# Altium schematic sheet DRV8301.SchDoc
size 558 x 431 mm; Engineer: Nicholas Oborny; Revision: A.1; Name: Nicholas Oborny; Start Date: 7/23/2012
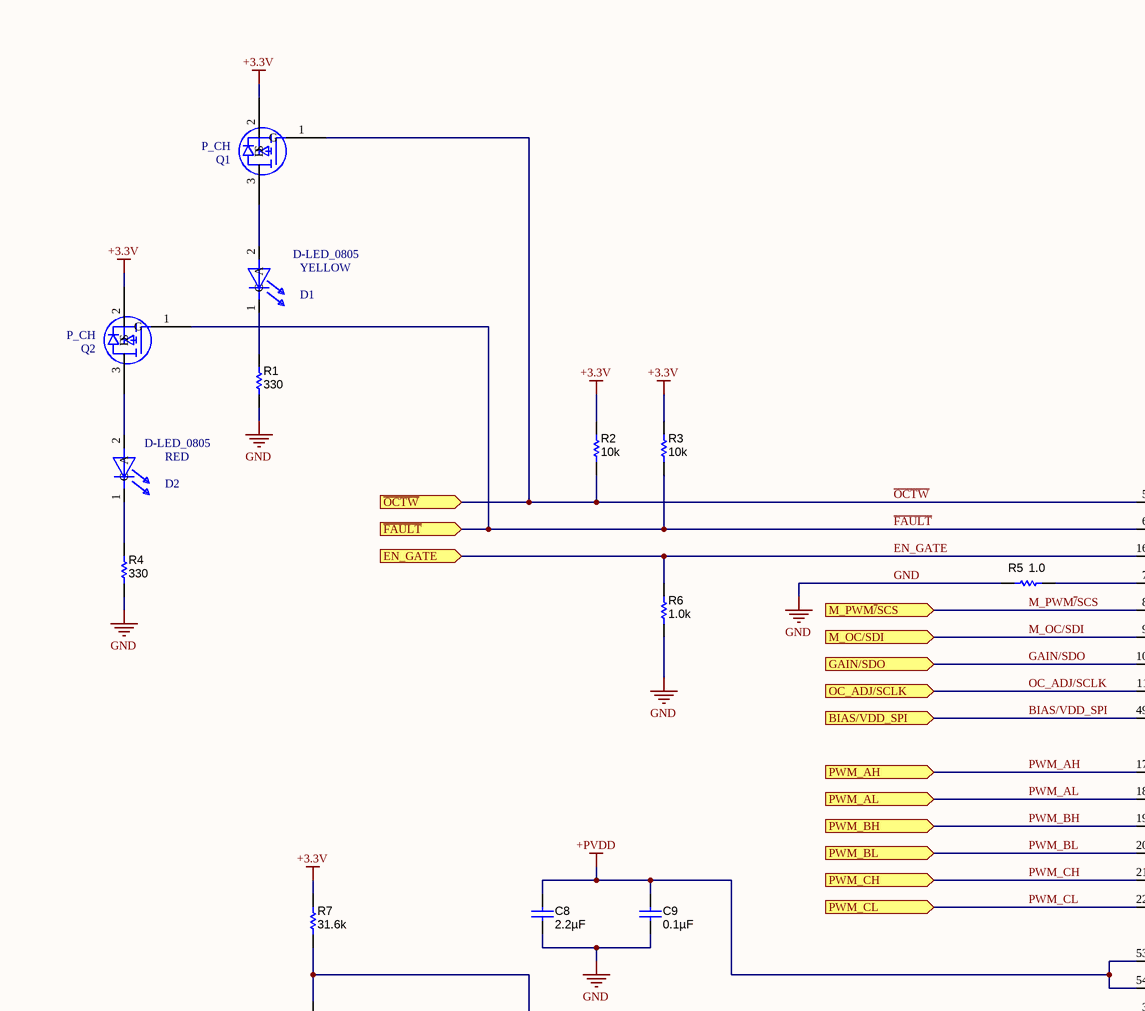
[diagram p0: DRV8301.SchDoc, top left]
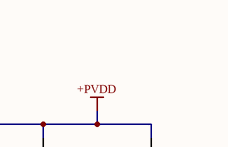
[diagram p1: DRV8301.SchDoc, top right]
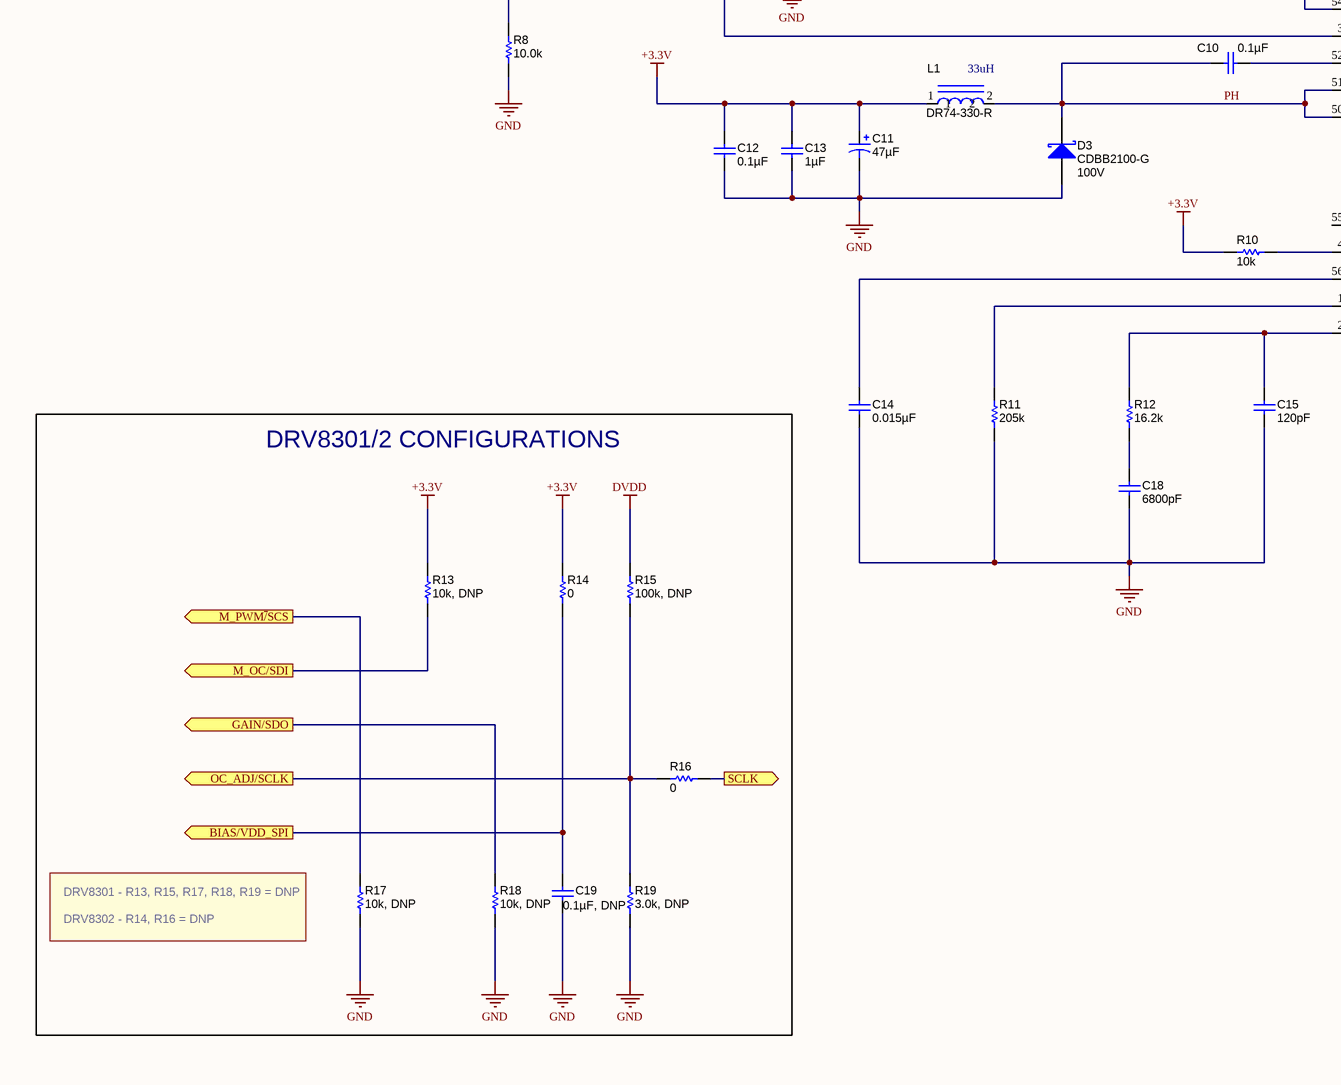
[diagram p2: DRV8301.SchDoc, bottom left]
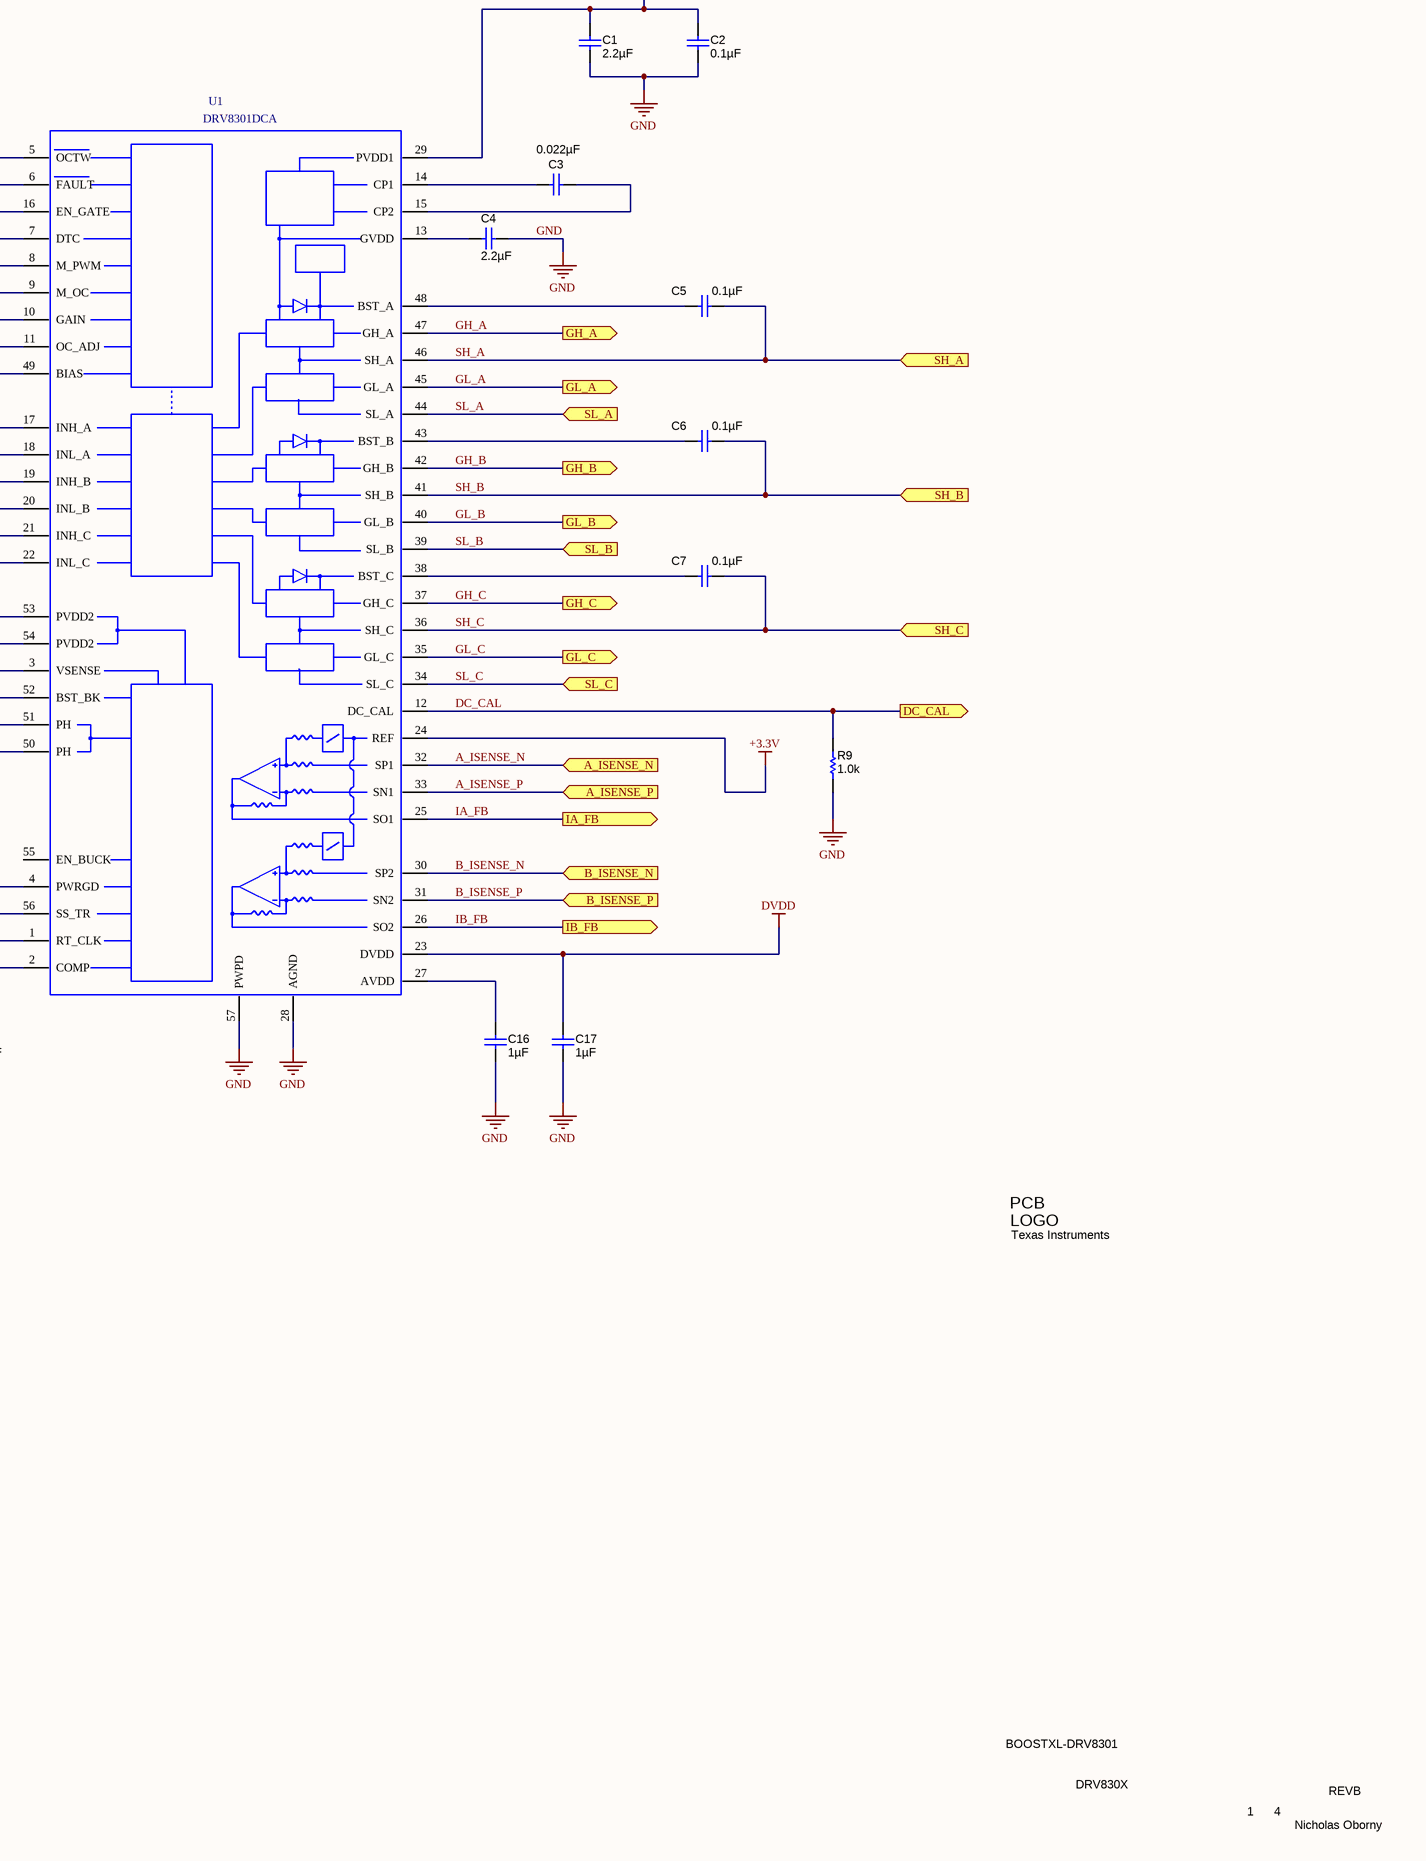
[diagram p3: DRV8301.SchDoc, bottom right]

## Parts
C1  ValueDisplayed: 2.2µF  [1210L]  (hidden comment: GRM32ER72A225KA35L)
C2  ValueDisplayed: 0.1µF  [0603L]  (hidden comment: GRM188R72A104KA35D)
C3  ValueDisplayed: 0.022µF  [0603L]  (hidden comment: C1608X7R1H223K)
C4  ValueDisplayed: 2.2µF  [0805L]  (hidden comment: GRM219R61E225KA12D)
C5  ValueDisplayed: 0.1µF  [0603L]  (hidden comment: C1608X7R1H104K)
C6  ValueDisplayed: 0.1µF  [0603L]  (hidden comment: C1608X7R1H104K)
C7  ValueDisplayed: 0.1µF  [0603L]  (hidden comment: C1608X7R1H104K)
C8  ValueDisplayed: 2.2µF  [1210L]  (hidden comment: GRM32ER72A225KA35L)
C9  ValueDisplayed: 0.1µF  [0603L]  (hidden comment: GRM188R72A104KA35D)
C10  ValueDisplayed: 0.1µF  [0603L]  (hidden comment: C1608X7R1H104K)
C11  ValueDisplayed: 47µF  [SM_RADIAL_D]  (hidden comment: EEE-FK1E470P)
C12  ValueDisplayed: 0.1µF  [0603L]  (hidden comment: C1608X7R1E104K)
C13  ValueDisplayed: 1µF  [0603L]  (hidden comment: C1608X5R1E105K080AC)
C14  ValueDisplayed: 0.015µF  [0603L]  (hidden comment: GRM188R71H153KA01D)
C15  ValueDisplayed: 120pF  [0603L]  (hidden comment: GRM1885C1H121JA01D)
C16  ValueDisplayed: 1µF  [0603L]  (hidden comment: GRM188R61E105KA12D)
C17  ValueDisplayed: 1µF  [0603L]  (hidden comment: GRM188R61E105KA12D)
C18  ValueDisplayed: 6800pF  [0603L]  (hidden comment: GRM188R71H682KA01D)
C19  ValueDisplayed: 0.1µF, DNP  [0603L]  (hidden comment: C1608X7R1E104K)
D1  D-LED_0805  value YELLOW  [LED_0805]
D2  D-LED_0805  value RED  [LED_0805]
D3  CDBB2100-G  value 100V  [SMB]
L1  DR74-330-R  value 33uH  [IND_DR74]
Logo1  Texas Instruments  [TI_Symbol_Overlay_Small]  (no BOM)
Q1  value P_CH  [SOT-23]  (hidden comment: TR_PFET_SOT23)
Q2  value P_CH  [SOT-23]  (hidden comment: TR_PFET_SOT23)
R1  value 330  [0603L]  (hidden comment: CRCW0603330RJNEA)
R2  value 10k  [0603L]  (hidden comment: CRCW060310K0JNEA)
R3  value 10k  [0603L]  (hidden comment: CRCW060310K0JNEA)
R4  value 330  [0603L]  (hidden comment: CRCW0603330RJNEA)
R5  value 1.0  [0603L]  (hidden comment: CRCW06031R00JNEA)
R6  value 1.0k  [0603L]  (hidden comment: CRCW06031K00JNEA)
R7  value 31.6k  [0603L]  (hidden comment: CRCW060331K6FKEA)
R8  value 10.0k  [0603L]  (hidden comment: RG1608P-103-B-T5)
R9  value 1.0k  [0603L]  (hidden comment: CRCW06031K00JNEA)
R10  value 10k  [0603L]  (hidden comment: CRCW060310K0JNEA)
R11  value 205k  [0603L]  (hidden comment: CRCW0603205KFKEA)
R12  value 16.2k  [0603L]  (hidden comment: CRCW060316K2FKEA)
R13  value 10k, DNP  [0603L]  (hidden comment: CRCW060310K0JNEA)
R14  value 0  [0603L]  (hidden comment: CRCW06030000Z0EA)
R15  value 100k, DNP  [0603L]  (hidden comment: CRCW0603100KJNEA)
R16  value 0  [0603L]  (hidden comment: CRCW06030000Z0EA)
R17  value 10k, DNP  [0603L]  (hidden comment: CRCW060310K0JNEA)
R18  value 10k, DNP  [0603L]  (hidden comment: CRCW060310K0JNEA)
R19  value 3.0k, DNP  [0603L]  (hidden comment: CRCW06033K00JNEA)
U1  DRV8301DCA  [DCA_56P]

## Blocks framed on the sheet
DRV8301/2 CONFIGURATIONS: C19 R13-R19

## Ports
A_ISENSE_N, A_ISENSE_P, B_ISENSE_N, B_ISENSE_P, BIAS/VDD_SPI, DC_CAL, EN_GATE, GAIN/SDO, GH_A, GH_B, GH_C, GL_A, GL_B, GL_C, IA_FB, IB_FB, M_OC/SDI, M_PWM~{/}SCS, OC_ADJ/SCLK, PWM_AH, PWM_AL, PWM_BH, PWM_BL, PWM_CH, PWM_CL, SCLK, SH_A, SH_B, SH_C, SL_A, SL_B, SL_C, ~{FAULT}, ~{OCTW}

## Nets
+3.3V: C11.1(+) C12.1 C13.1 L1.1 Q1.2(S) Q2.2(S) R2.2 R3.2 R7.2 R10.2 R13.2 R14.2 U1.24(REF)
+PVDD: C1.1 C2.1 C8.1 C9.1 U1.29(PVDD1) U1.53(PVDD2) U1.54(PVDD2)
DVDD: C17.1 R15.1 U1.23(DVDD)
GND: C1.2 C2.2 C4.2 C8.2 C9.2 C11.2(-) C12.2 C13.2 C14.2 C15.2 C16.2 C17.2 C18.2 C19.2 D3.2(A) R1.1 R4.1 R5.1 R6.1 R8.1 R9.1 R11.1 R17.1 R18.1 R19.1 U1.28(AGND) U1.57(PWPD)
~{FAULT}: Q2.1(G) R3.1 U1.6(FAULT) ; port ~{FAULT}
~{OCTW}: Q1.1(G) R2.1 U1.5(OCTW) ; port ~{OCTW}
A_ISENSE_N: U1.32(SP1) ; port A_ISENSE_N
A_ISENSE_P: U1.33(SN1) ; port A_ISENSE_P
B_ISENSE_N: U1.30(SP2) ; port B_ISENSE_N
B_ISENSE_P: U1.31(SN2) ; port B_ISENSE_P
BIAS/VDD_SPI: C19.1 R14.1 U1.49(BIAS) ; port BIAS/VDD_SPI
DC_CAL: R9.2 U1.12(DC_CAL) ; port DC_CAL
EN_GATE: R6.2 U1.16(EN_GATE) ; port EN_GATE
GAIN/SDO: R18.2 U1.10(GAIN) ; port GAIN/SDO
GH_A: U1.47(GH_A) ; port GH_A
GH_B: U1.42(GH_B) ; port GH_B
GH_C: U1.37(GH_C) ; port GH_C
GL_A: U1.45(GL_A) ; port GL_A
GL_B: U1.40(GL_B) ; port GL_B
GL_C: U1.35(GL_C) ; port GL_C
IA_FB: U1.25(SO1) ; port IA_FB
IB_FB: U1.26(SO2) ; port IB_FB
M_OC/SDI: R13.1 U1.9(M_OC) ; port M_OC/SDI
M_PWM~{/}SCS: R17.2 U1.8(M_PWM) ; port M_PWM~{/}SCS
OC_ADJ/SCLK: R15.2 R16.2 R19.2 U1.11(OC_ADJ) ; port OC_ADJ/SCLK
PH: C10.1 D3.1(K) L1.2 U1.50(PH) U1.51(PH)
PWM_AH: U1.17(INH_A) ; port PWM_AH
PWM_AL: U1.18(INL_A) ; port PWM_AL
PWM_BH: U1.19(INH_B) ; port PWM_BH
PWM_BL: U1.20(INL_B) ; port PWM_BL
PWM_CH: U1.21(INH_C) ; port PWM_CH
PWM_CL: U1.22(INL_C) ; port PWM_CL
SCLK: R16.1 ; port SCLK
SH_A: C5.2 U1.46(SH_A) ; port SH_A
SH_B: C6.2 U1.41(SH_B) ; port SH_B
SH_C: C7.2 U1.36(SH_C) ; port SH_C
SL_A: U1.44(SL_A) ; port SL_A
SL_B: U1.39(SL_B) ; port SL_B
SL_C: U1.34(SL_C) ; port SL_C
NetC3_1: C3.1 U1.14(CP1)
NetC3_2: C3.2 U1.15(CP2)
NetC4_1: C4.1 U1.13(GVDD)
NetC5_1: C5.1 U1.48(BST_A)
NetC6_1: C6.1 U1.43(BST_B)
NetC7_1: C7.1 U1.38(BST_C)
NetC10_2: C10.2 U1.52(BST_BK)
NetC14_1: C14.1 U1.56(SS_TR)
NetC15_1: C15.1 R12.2 U1.2(COMP)
NetC16_1: C16.1 U1.27(AVDD)
NetC18_1: C18.1 R12.1
NetD1_1: D1.1(C) R1.2
NetD1_2: D1.2(A) Q1.3(D)
NetD2_1: D2.1(C) R4.2
NetD2_2: D2.2(A) Q2.3(D)
NetR5_2: R5.2 U1.7(DTC)
NetR7_1: R7.1 R8.2 U1.3(VSENSE)
NetR10_1: R10.1 U1.4(PWRGD)
NetR11_2: R11.2 U1.1(RT_CLK)

Not connected (* = marked no-connect by the designer): U1 55(EN_BUCK)

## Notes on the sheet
- DRV8301 - R13, R15, R17, R18, R19 = DNP
- DRV8302 - R14, R16 = DNP
- BOOSTXL-DRV8301
- DRV830X
- 1
- 4
- REVB
- Nicholas Oborny

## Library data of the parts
C1 C8 = GRM32ER72A225KA35L: CAP, CERM, 2.2uF, 100V, +/-10%, X7R, 1210; Manufacturer: MuRata; Polarized: N; CompType: Capacitor; U/M: EA; Cap_F: 0.0000022; Tolerance_%: 10; ESR_Ohm: 0.007; Value1: 0.007 ohm; VDC_V: 100; IRMS_A: 4.4; TaMin_C: -55; TaMax_C: 125; Cap_Case: 1210
C2 C9 = GRM188R72A104KA35D: CAP, CERM, 0.1uF, 100V, +/-10%, X7R, 0603; Manufacturer: MuRata; Polarized: N; CompType: Capacitor; U/M: EA; Cap_F: 0.0000001; Tolerance_%: 10; Value1: Unknown; VDC_V: 100; TaMin_C: -55; TaMax_C: 125; Cap_Case: 0603
C3 = C1608X7R1H223K: CAP, CERM, 0.022uF, 50V, +/-10%, X7R, 0603; Manufacturer: TDK; Polarized: N; CompType: Capacitor; U/M: EA; Cap_F: 0.000000022; Tolerance_%: 10; ESR_Ohm: 0.0383; Value1: 0.0383 ohm; VDC_V: 50; TaMin_C: -55; TaMax_C: 125; Cap_Case: 0603
C4 = GRM219R61E225KA12D: CAP, CERM, 2.2uF, 25V, +/-10%, X5R, 0805; Manufacturer: MuRata; Polarized: N; CompType: Capacitor; U/M: EA; Cap_F: 0.0000022; Tolerance_%: 10; ESR_Ohm: 0.006; Value1: 0.006 ohm; VDC_V: 25; TaMin_C: -55; TaMax_C: 85; Cap_Case: 0805
C5-C7 C10 = C1608X7R1H104K: CAP, CERM, 0.1uF, 50V, +/-10%, X7R, 0603; Manufacturer: TDK; Polarized: N; CompType: Capacitor; U/M: EA; Cap_F: 0.0000001; Tolerance_%: 10; ESR_Ohm: 0.017; Value1: 0.017 ohm; VDC_V: 50; TaMin_C: -55; TaMax_C: 125; Cap_Case: 0603
C11 = EEE-FK1E470P: CAP, AL, 47uF, 25V, +/-20%, 0.36 ohm, SMD; Manufacturer: Panasonic; Polarized: Y; CompType: Capacitor; U/M: EA; Cap_F: 0.000047; Tolerance_%: 20; VDC_V: 25; ESR_Ohm: 0.36; IRMS_A: 0.24; TaMin_C: -55; TaMax_C: 105; Cap_Case: D
C12 C19 = C1608X7R1E104K: CAP, CERM, 0.1uF, 25V, +/-10%, X7R, 0603; Manufacturer: TDK; Polarized: N; CompType: Capacitor; U/M: EA; Cap_F: 0.0000001; Tolerance_%: 10; ESR_Ohm: 0.017; Value1: 0.017 ohm; VDC_V: 25; TaMin_C: -55; TaMax_C: 125; Cap_Case: 0603
C13 = C1608X5R1E105K080AC: CAP, CERM, 1uF, 25V, +/-10%, X5R, 0603; Manufacturer: TDK; Polarized: N; CompType: Capacitor; U/M: EA; Cap_F: 0.000001; Tolerance_%: 10; Value1: Unknown; VDC_V: 25; TaMin_C: -55; TaMax_C: 85; Cap_Case: 0603
C14 = GRM188R71H153KA01D: CAP, CERM, 0.015uF, 50V, +/-10%, X7R, 0603; Manufacturer: MuRata; Polarized: N; CompType: Capacitor; U/M: EA; Cap_F: 0.000000015; Tolerance_%: 10; Value1: Unknown; VDC_V: 50; TaMin_C: -55; TaMax_C: 125; Cap_Case: 0603
C15 = GRM1885C1H121JA01D: CAP, CERM, 120pF, 50V, +/-5%, C0G/NP0, 0603; Manufacturer: MuRata; Polarized: N; CompType: Capacitor; U/M: EA; Cap_F: 0.00000000012; Tolerance_%: 5; Value1: Unknown; VDC_V: 50; TaMin_C: -55; TaMax_C: 125; Cap_Case: 0603
C16 C17 = GRM188R61E105KA12D: CAP, CERM, 1uF, 25V, +/-10%, X5R, 0603; Manufacturer: MuRata; Polarized: N; CompType: Capacitor; U/M: EA; Cap_F: 0.000001; Tolerance_%: 10; Value1: Unknown; VDC_V: 25; TaMin_C: -55; TaMax_C: 85; Cap_Case: 0603
C18 = GRM188R71H682KA01D: CAP, CERM, 6800pF, 50V, +/-10%, X7R, 0603; Manufacturer: MuRata; Polarized: N; CompType: Capacitor; U/M: EA; Cap_F: 0.0000000068; Tolerance_%: 10; Value1: Unknown; VDC_V: 50; TaMin_C: -55; TaMax_C: 125; Cap_Case: 0603
D1 = D-LED_0805: LED THIN 585NM YEL DIFF 0805 SMD; PartNumber: SML-LXT0805YW-TR; Manufacturer: Lumex Opto/Components Inc; Vendor Part #: 67-1554-1-ND; PCB DECAL: LED-0805DA; Vendor: DigiKey
D2 = D-LED_0805: LED THIN660NM SUPRED DIFF0805SMD; PartNumber: SML-LXT0805SRW-TR; Manufacturer: Lumex Opto/Components Inc; Vendor Part #: 67-1555-1-ND; Vendor: DigiKey
D3 = CDBC5100-G: Diode, Schottky, 100V, 2A, SMB; Manufacturer: Comchip Technology; U/M: EA; Vf_V: 0.85; Value2: 0.85V; Io_A: 2; Vr_V: 100; TJmax_C: 125
L1 = IND_DR74-XXX: INDUCTOR SHIELD PWR 33UH SMD; Manufacturer: Cooper Bussmann; Area: 122500
Logo1 = TI_Logo: Texas Instrument Corporate Signature; SymbolCreator: codlsc
Q1 Q2 = TR_PFET_SOT23: MOSFET P-CH 8V 5.4A SOT23-3; PartNumber: SI2325DS-T1-E3; Manufacturer: Vishey Siliconix; Vendor Part #: S12325DS-T1-E3CT-ND; Vendor: DigiKey
R1 R4 = CRCW0603330RJNEA: RES, 330 ohm, 5%, 0.1W, 0603; Manufacturer: Vishay-Dale; CompType: Resistor; Value_Code: 330R; Tolerance_%: 5; Power_W: 0.1; VDC_V: 75; TempCo: 200 ppm/C; EIA_Code: E24; U/M: EA
R2 R3 R10 = CRCW060310K0JNEA: RES, 10k ohm, 5%, 0.1W, 0603; Manufacturer: Vishay-Dale; CompType: Resistor; Res_ohm: 10000; Value_Code: 10k0; Tolerance_%: 5; Power_W: 0.1; VDC_V: 75; TempCo: 200 ppm/C; EIA_Code: E24; U/M: EA
R5 = CRCW06031R00JNEA: RES, 1.0 ohm, 5%, 0.1W, 0603; Manufacturer: Vishay-Dale; CompType: Resistor; Res_ohm: 1; Value_Code: 1R00; Tolerance_%: 5; Power_W: 0.1; VDC_V: 75; TempCo: 200 ppm/C; EIA_Code: E24; U/M: EA
R6 R9 = CRCW06031K00JNEA: RES, 1.0k ohm, 5%, 0.1W, 0603; Manufacturer: Vishay-Dale; CompType: Resistor; Res_ohm: 1000; Value_Code: 1k00; Tolerance_%: 5; Power_W: 0.1; VDC_V: 75; TempCo: 200 ppm/C; EIA_Code: E24; U/M: EA
R7 = CRCW060331K6FKEA: RES, 31.6k ohm, 1%, 0.1W, 0603; Manufacturer: Vishay-Dale; CompType: Resistor; Res_ohm: 31600; Value_Code: 31k6; Tolerance_%: 1; Power_W: 0.1; VDC_V: 75; TempCo: 100 ppm/C; EIA_Code: E96; U/M: EA
R8 = RG1608P-103-B-T5: RES, 10.0k ohm, 0.1%, 0.1W, 0603; Manufacturer: Susumu Co Ltd; CompType: Resistor; Res_ohm: 10000; Value_Code: 10k0; Tolerance_%: 0.1; VDC_V: 75; TempCo: 25 ppm/C; EIA_Code: E192; U/M: EA
R11 = CRCW0603205KFKEA: RES, 205k ohm, 1%, 0.1W, 0603; Manufacturer: Vishay-Dale; CompType: Resistor; Res_ohm: 205000; Tolerance_%: 1; Power_W: 0.1; VDC_V: 75; TempCo: 100 ppm/C; EIA_Code: E96; U/M: EA
R12 = CRCW060316K2FKEA: RES, 16.2k ohm, 1%, 0.1W, 0603; Manufacturer: Vishay-Dale; CompType: Resistor; Res_ohm: 16200; Value_Code: 16k2; Tolerance_%: 1; Power_W: 0.1; VDC_V: 75; TempCo: 100 ppm/C; EIA_Code: E96; U/M: EA
R13 R17 R18 = CRCW060310K0JNEA: RES, 10k ohm, 5%, 0.1W, 0603; Manufacturer: Vishay-Dale; Alternate Manufacturer: DNP; CompType: Resistor; Res_ohm: 10000; Value_Code: 10k0; Tolerance_%: 5; Power_W: 0.1; VDC_V: 75; TempCo: 200 ppm/C; EIA_Code: E24; U/M: EA
R14 R16 = CRCW06030000Z0EA: RES, 0 ohm, 5%, 0.1W, 0603; Manufacturer: Vishay-Dale; CompType: Resistor; Value_Code: 0000; Tolerance_%: 5; Power_W: 0.1; VDC_V: 75; TempCo: 200 ppm/C; EIA_Code: E24; U/M: EA
R15 = CRCW0603100KJNEA: RES, 100k ohm, 5%, 0.1W, 0603; Manufacturer: Vishay-Dale; Alternate Manufacturer: DNP; CompType: Resistor; Res_ohm: 100000; Tolerance_%: 5; Power_W: 0.1; VDC_V: 75; TempCo: 200 ppm/C; EIA_Code: E24; U/M: EA
R19 = CRCW06033K00JNEA: RES, 3.0k ohm, 5%, 0.1W, 0603; Manufacturer: Vishay-Dale; Alternate Manufacturer: DNP; CompType: Resistor; Res_ohm: 3000; Value_Code: 3k00; Tolerance_%: 5; Power_W: 0.1; VDC_V: 75; TempCo: 200 ppm/C; EIA_Code: E24; U/M: EA
U1 = DRV8302DCA_ERIC: IC, 3 Phase Pre-Driver with Dual Current Shunt Amplifiers and Buck Regulator-Hardware Controlled; Manufacturer: Texas Instruments; Area: 154.44 mm; Vendor: Supplied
